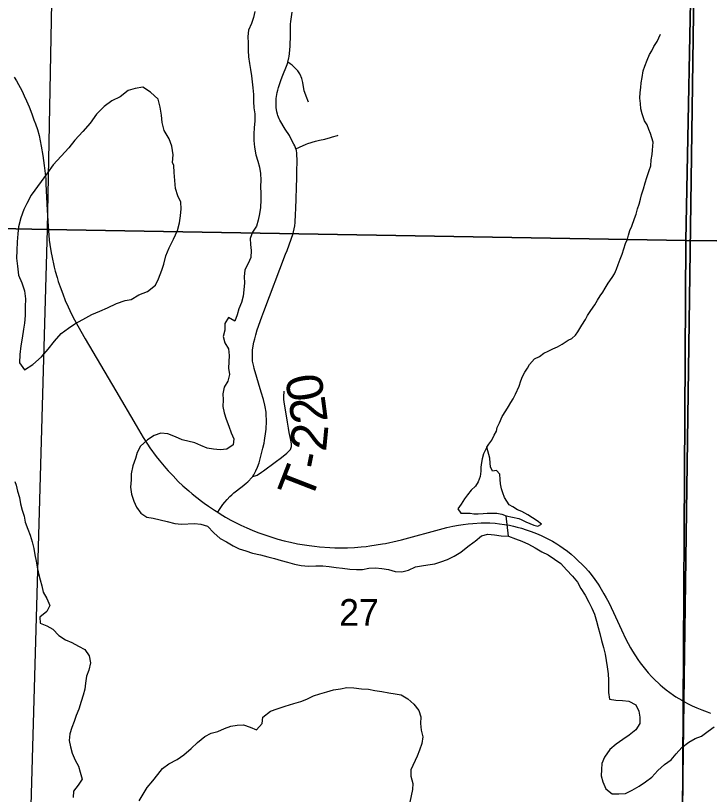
# Model space of a CAD drawing. Extents: x 0 to 34, y 0 to 22.
# Drawn here: x 19.172 to 20.261, y 16.809 to 18.033 of the extents above; entities that cross this region are included whole.
import ezdxf

# ---------------------------------------------------------------- set-up
doc = ezdxf.new("R2010")
doc.units = 0
for name, color, linetype in [('GM_X_Corporation', 7, 'Continuous'), ('GM_X_Major_Lake', 7, 'Continuous'), ('GM_X_Minor_River', 7, 'Continuous'), ('GM_X_Section_Text', 7, 'Continuous'), ('GM_X_Township_Road', 7, 'Continuous'), ('GM_X_Township_Road_Text', 7, 'Continuous'), ('GM_X_US_Route', 7, 'Continuous')]:
    doc.layers.add(name, color=color, linetype=linetype)

msp = doc.modelspace()

# ---------------------------------------------------------------- linework, layer by layer
at = {"layer": 'GM_X_Corporation'}
for points in [[(18.6, 19.2331), (18.6, 14.6606), (18.9216, 14.6592), (19.4007, 14.6554), (19.8855, 14.6528), (20.2016, 14.6512), (20.203, 14.81), (20.1987, 15.2691), (20.2208, 16.9558), (20.2471, 18.8539), (20.254, 19.2058), (20.065, 19.208), (18.9898, 19.2261)], [(18.6, 18.7129), (18.6, 17.7098), (19.222, 17.6968), (19.241, 18.7106)], [(19.241, 18.7106), (20.2437, 18.6978), (20.2237, 17.6792), (19.222, 17.6968)], [(21.2582, 18.6819), (21.2422, 17.6682), (20.2237, 17.6792), (20.2437, 18.6978)], [(18.6, 17.7098), (18.6, 16.7037), (19.1937, 16.6992), (19.222, 17.6968)], [(20.2237, 17.6792), (20.2179, 16.6698), (19.1937, 16.6992), (19.222, 17.6968)], [(21.2422, 17.6682), (21.2309, 16.6512), (20.2179, 16.6698), (20.2237, 17.6792)]]:
    msp.add_lwpolyline(points, close=True, dxfattribs=at)
msp.add_lwpolyline([(25.4, 14.4307), (25.4, 19.0068), (24.5766, 19.0222), (24.3186, 19.0261), (24.3186, 19.1409), (24.169, 19.1418), (23.786, 19.1434), (23.5499, 19.1465), (23.3329, 19.1508), (22.6423, 19.1645), (21.8956, 19.1793), (21.7744, 19.1817), (21.5297, 19.1865), (21.2652, 19.1913), (20.8916, 19.1966), (20.254, 19.2058), (20.2471, 18.8539), (20.2208, 16.9558), (20.1987, 15.2691)], dxfattribs=at)
at = {"layer": 'GM_X_Major_Lake'}
for points in [[(19.5473, 18.0389), (19.5451, 18.0295), (19.542, 18.02), (19.5375, 18.0097), (19.536, 17.9999), (19.5368, 17.9892), (19.5368, 17.9775), (19.5372, 17.968), (19.5387, 17.9574), (19.5402, 17.9479), (19.5421, 17.938), (19.5432, 17.9285), (19.544, 17.9191), (19.5452, 17.9084), (19.5452, 17.8978), (19.5459, 17.8876), (19.5471, 17.8781), (19.5471, 17.8675), (19.5463, 17.8565), (19.5456, 17.8466), (19.5456, 17.8364), (19.5467, 17.8257), (19.5486, 17.814), (19.552, 17.8041), (19.5547, 17.7943), (19.5562, 17.7844), (19.5566, 17.7742), (19.5562, 17.7639), (19.5566, 17.7529), (19.5566, 17.7431), (19.5563, 17.7313), (19.5544, 17.721), (19.5525, 17.7112), (19.5498, 17.7017), (19.5434, 17.6922), (19.54, 17.6827), (19.5404, 17.6729), (19.5415, 17.6634), (19.5408, 17.6527), (19.5366, 17.6433), (19.5317, 17.633), (19.5306, 17.6224), (19.531, 17.6129), (19.5299, 17.6019), (19.5287, 17.592), (19.5265, 17.5818), (19.5223, 17.5719), (19.5197, 17.5624), (19.5159, 17.5526), (19.5057, 17.5586), (19.5, 17.5491)], [(19.4202, 17.7971), (19.4182, 17.8016), (19.4189, 17.8141), (19.4172, 17.8274), (19.413, 17.8391), (19.4049, 17.8519), (19.4017, 17.8644), (19.4009, 17.8761), (19.3988, 17.8886), (19.3953, 17.9011), (19.3834, 17.9124), (19.3712, 17.9202), (19.3595, 17.9182), (19.3482, 17.9147), (19.3358, 17.9051), (19.323, 17.8985), (19.3109, 17.89), (19.2985, 17.8778), (19.2885, 17.8636), (19.2772, 17.8503), (19.2649, 17.8369), (19.2555, 17.8246), (19.2431, 17.812), (19.2308, 17.7982), (19.2218, 17.7856), (19.1964, 17.7505)], [(19.1964, 17.7505), (19.1893, 17.7375), (19.1848, 17.728), (19.1797, 17.7151), (19.176, 17.701), (19.175, 17.6896), (19.174, 17.6771), (19.1737, 17.6638), (19.1731, 17.6517), (19.1747, 17.6388), (19.1764, 17.6251), (19.1814, 17.6127), (19.1857, 17.6002), (19.1874, 17.5877), (19.1867, 17.5752), (19.1865, 17.5615), (19.1858, 17.5494), (19.184, 17.5399), (19.1819, 17.5258), (19.1801, 17.5137), (19.1784, 17.5004), (19.1777, 17.4871), (19.1858, 17.4762), (19.199, 17.4847), (19.2125, 17.4966), (19.223, 17.5084), (19.2327, 17.521), (19.2432, 17.5333), (19.2549, 17.5417), (19.2646, 17.5483), (19.2775, 17.5552), (19.2914, 17.5629), (19.3038, 17.5684), (19.3159, 17.5734), (19.3299, 17.5804), (19.3435, 17.5851), (19.3533, 17.5867), (19.3653, 17.594), (19.3789, 17.5994), (19.3913, 17.6094), (19.3962, 17.6193), (19.4013, 17.6327), (19.4043, 17.6422), (19.4076, 17.6551), (19.4127, 17.668), (19.4194, 17.6814), (19.4257, 17.6951), (19.429, 17.7069), (19.4308, 17.7179), (19.4315, 17.7293), (19.431, 17.7395), (19.4263, 17.7493), (19.4228, 17.761), (19.4216, 17.7735), (19.4207, 17.7861), (19.4202, 17.7971)], [(19.5, 17.5491), (19.5, 17.5385), (19.4974, 17.5283), (19.5004, 17.5188), (19.5057, 17.5093), (19.5072, 17.4987), (19.5057, 17.479), (19.5076, 17.4687), (19.5046, 17.4585), (19.4993, 17.449), (19.497, 17.4387), (19.4974, 17.4289), (19.4971, 17.4186), (19.499, 17.4084), (19.5024, 17.3989), (19.5062, 17.3875), (19.5103, 17.3773), (19.5145, 17.3678), (19.5134, 17.3583), (19.5032, 17.3515), (19.4929, 17.3507), (19.4823, 17.3515), (19.4725, 17.353), (19.4626, 17.3571), (19.4528, 17.3617), (19.4331, 17.3662), (19.4225, 17.3711), (19.4108, 17.3757), (19.3998, 17.3768), (19.3892, 17.373), (19.3786, 17.3662), (19.3676, 17.3563), (19.3627, 17.3464), (19.3597, 17.3369), (19.3555, 17.3255), (19.3533, 17.313), (19.3529, 17.3032), (19.3522, 17.2918), (19.3537, 17.2808), (19.3575, 17.2701), (19.3616, 17.2607), (19.3685, 17.2508), (19.3779, 17.2448), (19.3878, 17.2432), (19.3988, 17.2406), (19.4094, 17.238), (19.4219, 17.2346), (19.4321, 17.2338), (19.4525, 17.2346), (19.4627, 17.2338), (19.473, 17.2304), (19.4828, 17.2202), (19.493, 17.2115), (19.5029, 17.2058), (19.5131, 17.1997), (19.5229, 17.1952), (19.5332, 17.1918), (19.5438, 17.1884), (19.5559, 17.1854), (19.5676, 17.1827), (19.5782, 17.1797), (19.5888, 17.1767), (19.5987, 17.174), (19.6096, 17.171), (19.6199, 17.1691), (19.6316, 17.168), (19.643, 17.1684), (19.6539, 17.1684), (19.6638, 17.1673), (19.6748, 17.1658), (19.685, 17.1646), (19.6963, 17.1631), (19.7066, 17.1624), (19.7164, 17.1624), (19.7262, 17.1647), (19.7368, 17.1654), (19.7467, 17.1643), (19.7573, 17.1624), (19.7675, 17.1594), (19.7781, 17.1587), (19.7883, 17.1617), (19.7993, 17.1666), (19.8091, 17.1685), (19.819, 17.1697), (19.8296, 17.1716), (19.8394, 17.1746), (19.8496, 17.1785), (19.8602, 17.1834), (19.8705, 17.1899), (19.8814, 17.1986), (19.8913, 17.2058), (19.8932, 17.2069)], [(19.1703, 17.3009), (19.1724, 17.295), (19.1746, 17.2855), (19.1777, 17.2756), (19.1796, 17.2658), (19.1822, 17.2559), (19.1853, 17.2464), (19.1868, 17.237), (19.1909, 17.226), (19.1944, 17.2165), (19.1978, 17.2059), (19.2004, 17.1956), (19.2019, 17.1858), (19.2038, 17.1759), (19.2054, 17.1664), (19.2076, 17.1565), (19.2103, 17.1463), (19.213, 17.1368), (19.2152, 17.127), (19.2205, 17.1171), (19.2255, 17.1061), (19.2209, 17.0966), (19.21, 17.0879), (19.2103, 17.0784), (19.2206, 17.0739), (19.2304, 17.0689), (19.2395, 17.0587), (19.2501, 17.0519), (19.26, 17.0477), (19.2702, 17.042), (19.2804, 17.0367), (19.2872, 17.0269), (19.2891, 17.0159), (19.2865, 17.0045), (19.2831, 16.995), (19.2816, 16.984), (19.2804, 16.9745), (19.2778, 16.965), (19.2748, 16.9552), (19.271, 16.9434), (19.2668, 16.9335), (19.2638, 16.924), (19.26, 16.9142), (19.257, 16.9047), (19.2559, 16.894), (19.2578, 16.8842), (19.2604, 16.8743), (19.2654, 16.8629), (19.2703, 16.8535), (19.2733, 16.844), (19.276, 16.8334), (19.2699, 16.8239), (19.2627, 16.8144), (19.262, 16.8045)], [(19.8932, 17.2069), (19.903, 17.2157), (19.9132, 17.2183), (19.9234, 17.2172), (19.9337, 17.2157), (19.9454, 17.215), (19.9564, 17.2108), (19.9666, 17.207), (19.9768, 17.2021), (19.9874, 17.1968), (19.9976, 17.1904), (20.0075, 17.1854), (20.0177, 17.1786), (20.0276, 17.1718), (20.0367, 17.1619), (20.0461, 17.1521), (20.0537, 17.1426), (20.059, 17.1328), (20.0658, 17.1225), (20.0715, 17.1115), (20.0764, 17.102), (20.0802, 17.0922), (20.0836, 17.0816), (20.0863, 17.0717), (20.0886, 17.0622), (20.0912, 17.0508), (20.0947, 17.0402), (20.0973, 17.0296), (20.0985, 17.0194), (20.1004, 17.0099), (20.1019, 16.9985), (20.1026, 16.989), (20.1026, 16.9693), (20.1038, 16.9587), (20.114, 16.9575), (20.1246, 16.9568), (20.1345, 16.956), (20.1451, 16.95), (20.15, 16.9401), (20.1515, 16.9306), (20.1515, 16.9208), (20.1455, 16.9109), (20.1349, 16.9025), (20.125, 16.8957), (20.1144, 16.8881), (20.1046, 16.8801), (20.0959, 16.868), (20.0921, 16.8581), (20.0914, 16.8486), (20.091, 16.8384), (20.0933, 16.8289), (20.0982, 16.8179), (20.108, 16.8103), (20.1186, 16.81), (20.1292, 16.8107), (20.1398, 16.816), (20.1504, 16.8221), (20.1607, 16.8293), (20.1705, 16.8366), (20.1796, 16.8468), (20.1902, 16.8563), (20.2008, 16.8635), (20.2087, 16.873), (20.2174, 16.8829), (20.2284, 16.8913), (20.2382, 16.897), (20.2484, 16.9008), (20.2587, 16.9087), (20.2685, 16.9152)], [(19.3657, 16.7993), (19.3721, 16.8099), (19.3782, 16.8202), (19.3873, 16.8308), (19.3948, 16.8407), (19.4024, 16.8502), (19.4122, 16.8574), (19.4251, 16.8639), (19.4357, 16.8715), (19.4471, 16.8813), (19.4573, 16.8908), (19.4686, 16.9003), (19.4788, 16.9053), (19.4891, 16.9083), (19.4997, 16.9129), (19.5095, 16.9163), (19.5197, 16.9182), (19.5296, 16.9186), (19.5398, 16.9148), (19.5496, 16.9107), (19.5587, 16.9209), (19.5598, 16.9304), (19.5716, 16.9399), (19.5825, 16.9437), (19.595, 16.9479), (19.6083, 16.9521), (19.6192, 16.9551), (19.6291, 16.9589), (19.6393, 16.9643), (19.6495, 16.9673), (19.6601, 16.9704), (19.6707, 16.9734), (19.6817, 16.9749), (19.6915, 16.9772), (19.7025, 16.9765), (19.7146, 16.9753), (19.7256, 16.9746), (19.7358, 16.9727), (19.7468, 16.9708), (19.7574, 16.9689), (19.7673, 16.9674), (19.7771, 16.9655), (19.7873, 16.9595), (19.7968, 16.9511), (19.8047, 16.9413), (19.8078, 16.9314), (19.8074, 16.9208), (19.8085, 16.9102), (19.8108, 16.8999), (19.8093, 16.8893), (19.8055, 16.8787), (19.8021, 16.8692), (19.7923, 16.8479), (19.7923, 16.8381), (19.7953, 16.8263), (19.7946, 16.8168), (19.7908, 16.7971)]]:
    msp.add_lwpolyline(points, dxfattribs=at)
at = {"layer": 'GM_X_Minor_River'}
for p, q in [((19.942, 17.2471), (19.9618, 17.2426)), ((19.9454, 17.215), (19.942, 17.2471))]:
    msp.add_line(p, q, dxfattribs=at)
for points in [[(19.9113, 17.3547), (19.9147, 17.3593), (19.9194, 17.3655), (19.9227, 17.3735), (19.9264, 17.3797), (19.9278, 17.3854), (19.9311, 17.3931), (19.9355, 17.4027), (19.9415, 17.4119), (19.9455, 17.4184), (19.9492, 17.4249), (19.9526, 17.4307), (19.9562, 17.438), (19.9621, 17.4503), (19.965, 17.4587), (19.9676, 17.4656), (19.9709, 17.4725), (19.975, 17.4786), (19.9783, 17.4844), (19.9865, 17.4932), (19.994, 17.4972), (20.0011, 17.5026), (20.0079, 17.5057), (20.015, 17.5093), (20.0225, 17.5124), (20.0297, 17.5163), (20.0391, 17.5226), (20.0447, 17.5253), (20.0507, 17.5304), (20.0544, 17.5361), (20.0607, 17.5461), (20.0662, 17.5553), (20.0695, 17.5615), (20.0747, 17.5692), (20.0807, 17.578), (20.0851, 17.5857), (20.0895, 17.5922), (20.0936, 17.598), (20.0973, 17.6045), (20.1017, 17.6122), (20.1084, 17.6214), (20.1117, 17.6272), (20.115, 17.6341), (20.1176, 17.6414), (20.1205, 17.6502), (20.1238, 17.6578), (20.1267, 17.6662), (20.1292, 17.6746), (20.1321, 17.6815), (20.134, 17.6877), (20.1361, 17.6949), (20.139, 17.7018), (20.143, 17.7137), (20.1456, 17.7206), (20.1477, 17.729), (20.1503, 17.7362), (20.1524, 17.7443), (20.1542, 17.7508), (20.1575, 17.7607), (20.16, 17.7699), (20.1625, 17.7783), (20.1665, 17.7894), (20.1687, 17.7966), (20.1693, 17.8062), (20.1707, 17.8142), (20.1714, 17.821), (20.172, 17.8275), (20.1723, 17.8336), (20.1684, 17.8473), (20.1656, 17.8537), (20.1629, 17.8609), (20.159, 17.8673), (20.155, 17.8783), (20.1534, 17.8859), (20.1525, 17.8946), (20.1516, 17.903), (20.1523, 17.9117), (20.1529, 17.9197), (20.1539, 17.927), (20.1553, 17.9354), (20.1567, 17.9457), (20.1592, 17.9533), (20.1629, 17.9625), (20.1669, 17.9713), (20.1706, 17.9771), (20.1736, 17.984), (20.1787, 17.9917), (20.1842, 18.0035)], [(19.9618, 17.2426), (19.9651, 17.2413), (19.9728, 17.2373), (19.985, 17.2321), (19.9914, 17.2307), (19.9974, 17.2338), (19.9902, 17.239), (19.9829, 17.2435), (19.9756, 17.2483), (19.9661, 17.2535), (19.9596, 17.2565), (19.9524, 17.2609), (19.9466, 17.2643), (19.9428, 17.2699), (19.9393, 17.2756), (19.9365, 17.2832), (19.9345, 17.2892), (19.9329, 17.2972), (19.9324, 17.304), (19.9319, 17.3124), (19.9266, 17.318), (19.9201, 17.3172), (19.917, 17.3236), (19.9169, 17.3297), (19.9161, 17.3373), (19.9145, 17.343), (19.9129, 17.349), (19.9113, 17.3547), (19.9061, 17.344), (19.904, 17.3363), (19.9033, 17.3306), (19.9022, 17.3234), (19.902, 17.3169), (19.9009, 17.3085), (19.8977, 17.3005), (19.8936, 17.2932), (19.8869, 17.287), (19.8809, 17.2797), (19.8765, 17.2735), (19.8709, 17.265), (19.8661, 17.2581), (19.8704, 17.2513), (19.8764, 17.251), (19.8851, 17.2508), (19.8912, 17.2501), (19.898, 17.2498), (19.9056, 17.2503), (19.912, 17.2508), (19.9196, 17.2513), (19.9271, 17.251), (19.9351, 17.2496), (19.942, 17.2471)]]:
    msp.add_lwpolyline(points, dxfattribs=at)
at = {"layer": 'GM_X_Township_Road'}
for points in [[(19.4889, 17.2524), (19.4917, 17.257), (19.4971, 17.2647), (19.4999, 17.2681), (19.5036, 17.2724), (19.508, 17.2771), (19.5109, 17.2799), (19.5144, 17.2828), (19.5274, 17.2931), (19.5338, 17.2982), (19.5361, 17.3003), (19.5429, 17.3074), (19.5441, 17.3088), (19.5456, 17.311), (19.5469, 17.3132), (19.5489, 17.3173), (19.5514, 17.3234), (19.5538, 17.3301), (19.555, 17.3341), (19.5599, 17.3533), (19.5617, 17.3612), (19.5625, 17.3652), (19.5645, 17.3791), (19.5648, 17.3829), (19.5656, 17.3953), (19.565, 17.4071), (19.5648, 17.4096), (19.5633, 17.4183), (19.5627, 17.4209), (19.5606, 17.4297), (19.5572, 17.441), (19.5462, 17.4783), (19.5455, 17.4813), (19.5442, 17.4878), (19.5438, 17.4897), (19.5435, 17.4965), (19.5434, 17.4994), (19.5438, 17.5069), (19.5443, 17.5109), (19.5458, 17.5198), (19.5471, 17.5247), (19.5488, 17.5313), (19.5511, 17.5391), (19.5582, 17.5592), (19.5615, 17.5678), (19.5956, 17.6581), (19.5979, 17.6638), (19.6072, 17.6902), (19.608, 17.6929), (19.6091, 17.6975), (19.6099, 17.7023), (19.6105, 17.7077), (19.6113, 17.7208), (19.6116, 17.7291), (19.6133, 17.7783), (19.6134, 17.7857), (19.6135, 17.8063), (19.6133, 17.8133), (19.6132, 17.8163), (19.6124, 17.8205), (19.612, 17.8221), (19.6116, 17.8234), (19.6099, 17.8279), (19.6086, 17.8308), (19.604, 17.8393), (19.6014, 17.8441), (19.595, 17.8544), (19.5866, 17.8681), (19.5856, 17.8702), (19.5835, 17.8756), (19.5827, 17.8776), (19.5817, 17.8815), (19.581, 17.8849), (19.5806, 17.8879), (19.5808, 17.9022), (19.5812, 17.9054), (19.5823, 17.9118), (19.5831, 17.9154), (19.5844, 17.9198), (19.5879, 17.9306), (19.5904, 17.9362), (19.5979, 17.9559), (19.5983, 17.9571), (19.5989, 17.9596), (19.6006, 17.9661), (19.6011, 17.9684), (19.6018, 17.9731), (19.6023, 17.9786), (19.6027, 17.9845), (19.6031, 18.0018), (19.6033, 18.0192), (19.6036, 18.0232), (19.6056, 18.0381)], [(19.6317, 17.8964), (19.6277, 17.9058), (19.6256, 17.9115), (19.6248, 17.9144), (19.6224, 17.9275), (19.621, 17.9335), (19.6186, 17.9398), (19.6178, 17.9413), (19.6157, 17.9441), (19.6145, 17.9456), (19.6088, 17.9517), (19.6056, 17.9545), (19.6044, 17.9555), (19.6025, 17.9568), (19.5989, 17.9596)], [(19.6116, 17.8234), (19.6175, 17.8261), (19.628, 17.8306), (19.6305, 17.8315), (19.6424, 17.8351), (19.6485, 17.8367), (19.6569, 17.8387), (19.6661, 17.841), (19.6693, 17.8419), (19.6768, 17.8443), (19.6781, 17.8448)], [(19.5441, 17.3088), (19.548, 17.3097), (19.5494, 17.3102), (19.5508, 17.3109), (19.5578, 17.3154), (19.5608, 17.3175), (19.5791, 17.331), (19.5891, 17.3387), (19.5976, 17.3454), (19.5998, 17.3473), (19.6019, 17.3493), (19.6031, 17.351), (19.6039, 17.3526), (19.6045, 17.3544), (19.6047, 17.3556), (19.6049, 17.3586), (19.6048, 17.3599), (19.6032, 17.3682), (19.6013, 17.3776), (19.6001, 17.3843), (19.5985, 17.3938), (19.5935, 17.4259), (19.593, 17.4294), (19.5926, 17.4338), (19.5931, 17.4427)]]:
    msp.add_lwpolyline(points, dxfattribs=at)
at = {"layer": 'GM_X_US_Route'}
for points in [[(19.1697, 17.9359), (19.1731, 17.9299), (19.1818, 17.9136), (19.1853, 17.9065), (19.1888, 17.8988), (19.1929, 17.8891), (19.1971, 17.8782), (19.2005, 17.8687), (19.2027, 17.8626), (19.2059, 17.8537), (19.2086, 17.844), (19.2119, 17.8275), (19.2144, 17.813), (19.2164, 17.7969), (19.218, 17.7848), (19.2189, 17.7764), (19.2193, 17.768), (19.2212, 17.7267), (19.2227, 17.7018), (19.2232, 17.6948), (19.2245, 17.6798), (19.2253, 17.6728), (19.2276, 17.6597), (19.2284, 17.655), (19.2323, 17.6375), (19.2337, 17.6313), (19.2367, 17.6214), (19.2386, 17.6149), (19.2414, 17.6064), (19.2457, 17.5953), (19.2494, 17.5852), (19.254, 17.5751), (19.2596, 17.5634), (19.2639, 17.5548), (19.2692, 17.5452), (19.281, 17.5248), (19.329, 17.443), (19.3609, 17.3886), (19.3721, 17.37), (19.379, 17.3592), (19.3823, 17.3539), (19.3924, 17.3401), (19.3969, 17.3345), (19.4075, 17.3218), (19.4113, 17.3175), (19.4188, 17.3095), (19.4271, 17.301), (19.4344, 17.2939), (19.4434, 17.286), (19.449, 17.2813), (19.4633, 17.2698), (19.4675, 17.2667), (19.4745, 17.2618), (19.484, 17.2555), (19.4889, 17.2524), (19.4929, 17.2499), (19.501, 17.245), (19.5098, 17.2401), (19.5179, 17.2359), (19.5255, 17.2321), (19.5348, 17.2279), (19.5429, 17.2244), (19.5519, 17.2208), (19.5627, 17.217), (19.5738, 17.2133), (19.5836, 17.2103), (19.5934, 17.2076), (19.6031, 17.2054), (19.6143, 17.203), (19.6216, 17.2017), (19.6325, 17.2001), (19.6411, 17.199), (19.6485, 17.1983), (19.6651, 17.1972), (19.6728, 17.1968), (19.6827, 17.1966), (19.6925, 17.1968), (19.7036, 17.1973), (19.7139, 17.198), (19.722, 17.1988), (19.7279, 17.1996), (19.7478, 17.2027), (19.7526, 17.2036), (19.7705, 17.2076), (19.7773, 17.2093), (19.8428, 17.2269), (19.8487, 17.2283), (19.8578, 17.2304), (19.8669, 17.2321), (19.8744, 17.2334), (19.8821, 17.2344), (19.8892, 17.235), (19.9027, 17.2357), (19.9095, 17.2359), (19.9163, 17.2357), (19.9247, 17.2352), (19.9312, 17.2345), (19.9389, 17.2334), (19.947, 17.232), (19.9532, 17.2307), (19.9589, 17.2293), (19.9659, 17.2274), (19.9733, 17.2251), (19.9812, 17.2223), (19.9894, 17.2191), (19.9966, 17.216), (20.002, 17.2134), (20.0084, 17.2102), (20.0146, 17.2068), (20.0215, 17.2027), (20.0258, 17.1999), (20.0315, 17.196), (20.0378, 17.1913), (20.0438, 17.1866), (20.0497, 17.1814), (20.0555, 17.1759), (20.0607, 17.171), (20.0658, 17.1656), (20.0708, 17.1599), (20.0753, 17.1545), (20.081, 17.1471), (20.0862, 17.1397), (20.089, 17.1352), (20.0952, 17.1245), (20.0987, 17.118), (20.1027, 17.1106), (20.1103, 17.095), (20.1229, 17.0679), (20.1297, 17.0531), (20.1332, 17.0464), (20.1369, 17.0397), (20.1402, 17.0341), (20.1484, 17.0214), (20.1523, 17.016), (20.1604, 17.0057), (20.1647, 17.0005), (20.1706, 16.9942), (20.1732, 16.9916), (20.1837, 16.9816), (20.1872, 16.9785), (20.1931, 16.9737), (20.1988, 16.9693), (20.2042, 16.9654), (20.2083, 16.9627)], [(20.2083, 16.9627), (20.2174, 16.9572), (20.2218, 16.9547), (20.2272, 16.9518), (20.2335, 16.9486), (20.2412, 16.9452), (20.2488, 16.942), (20.2571, 16.9389), (20.2627, 16.937)]]:
    msp.add_lwpolyline(points, dxfattribs=at)

# ---------------------------------------------------------------- texts
at = {"layer": 'GM_X_Section_Text'}
msp.add_text('27', height=0.04186, rotation=0, dxfattribs=at).set_placement((19.6796, 17.0742))
at = {"layer": 'GM_X_Township_Road_Text'}
for s, rotation, p in [('0', 99.03, (19.6572, 17.432)), ('2', 97.4482, (19.662, 17.3956)), ('2', 84.4944, (19.6589, 17.3468)), ('-', 78.3362, (19.6532, 17.3173)), ('T', 68.7708, (19.6349, 17.2678))]:
    msp.add_text(s, height=0.0568, rotation=rotation, dxfattribs=at).set_placement(p)

doc.saveas('drawing.dxf')
